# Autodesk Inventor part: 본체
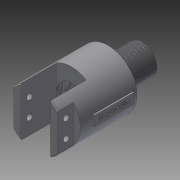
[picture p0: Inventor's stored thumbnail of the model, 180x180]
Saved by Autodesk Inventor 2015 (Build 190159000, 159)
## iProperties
Created: 2019-02
Part Number: 본체
Material: 일반
Document SubType Name: Modeling
Designer: now
Density: 1 g/cm^3
Appearance: 기본값
Author: now
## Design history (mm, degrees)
sketch "스케치1"
  geometry: C1 r 29 at (0, 0); 1 further point
  constraints: 1 centre point, 1 coincident
  dimensions: "d0" = 58 diameter of C1
extrude "돌출1" new body sketch "스케치1" distance "d1" = 74; taper "d2" = 0 deg
sketch "스케치2"
  geometry: C1 r 29 at (0, 0) reference; C2 r 13 at (0, 0)
  constraints: 1 centre point, 1 coincident
  dimensions: "d3" = 26 diameter of C2
extrude "돌출2" join sketch "스케치2" distance "d4" = 5; taper "d5" = 0 deg
sketch "스케치3"
  geometry: C1 r 13 at (0, 0) reference; C2 r 15 at (0, 0)
  constraints: 1 centre point, 1 coincident
  dimensions: "d6" = 30 diameter of C2
extrude "돌출3" join sketch "스케치3" distance "d7" = 29; taper "d8" = 0 deg
sketch "스케치4"
  geometry: L1 (-29, 0)-(-29, 74) reference; L2 (-29, 74)-(-13, 74) reference; L3 (-13, 74)-(-13, 79) reference; L4 (-13, 79)-(-15, 79) reference; L5 (-15, 79)-(-15, 108) reference; L6 (-15, 108)-(15, 108) reference; L7 (15, 108)-(15, 79) reference; L8 (15, 79)-(13, 79) reference; L9 (13, 79)-(13, 74) reference; L10 (13, 74)-(29, 74) reference; L11 (29, 74)-(29, 0) reference; L12 (29, 0)-(-29, 0) reference; L13 (15, 36)-(-15, 36); L14 (-15, 36)-(-15, 0); L15 (-15, 0)-(15, 0); L16 (15, 0)-(15, 36); L17 (15, 36)-(-15, 0); L18 (-15, 36)-(15, 0); 4 further points
  constraints: 12 end point, 4 midpoint, 2 parallel, 1 horizontal, 1 perpendicular, 1 point on line, 1 vertical alignment
  dimensions: "d9" = 36 distance of L15.end L13.start; "d10" = 30 distance of L13.start L13.end
extrude "돌출4" cut sketch "스케치4" stored distance "d11" = 29; taper "d12" = 0 deg
sketch "스케치5"
  geometry: L1 (-13, 79)-(-15, 79) reference; L2 (-15, 79)-(-15, 108) reference; L3 (-15, 108)-(15, 108) reference; L4 (15, 108)-(15, 79) reference; L5 (15, 79)-(13, 79) reference; L6 (13, 79)-(13, 74) reference; L7 (13, 74)-(29, 74) reference; L8 (29, 74)-(29, 0) reference; L9 (29, 0)-(15, 0) reference; L10 (15, 0)-(15, 36) reference; L11 (15, 36)-(-15, 36) reference; L12 (-15, 36)-(-15, 0) reference; L13 (-15, 0)-(-29, 0) reference; L14 (-29, 0)-(-29, 74) reference; L15 (-29, 74)-(-13, 74) reference; L16 (-13, 74)-(-13, 79) reference; L17 (-29, 16)-(-22, 16); L18 (-22, 16)-(-22, 0); L19 (-22, 0)-(-29, 0); L20 (-29, 0)-(-29, 16); 1 further point
  constraints: 8 end point, 2 parallel, 1 horizontal, 1 perpendicular
  dimensions: "d14" = 22 distance from line of point (0, 0) L18; "d15" = 16 distance of L17.end L18.end
extrude "돌출5" cut sketch "스케치5" stored distance "d16" = 29; taper "d17" = 0 deg
sketch "스케치6"
  geometry: L1 (0, 0)-(-37.789, 0) reference; 2 further points
  dimensions: "d18" = 9 distance from line of L1 point (-27.894, 9); "d19" = 9 horizontal distance of point (-18.894, 0) point (-27.894, 9)
hole "구멍1" sketch "스케치6" at (-27.894, 9) diameter "d20" = 6; stored, may be unused: countersink angle "d24" = 90 deg, drill point angle "d26" = 118 deg; dims "d21" = 6, "d22" = 4, "d23" = 2, "d25" = 8
sketch "스케치8"
  geometry: L1 (79, 13)-(79, 15) reference; L2 (79, 15)-(108, 15) reference; L3 (108, 15)-(108, -15) reference; L4 (108, -15)-(79, -15) reference; L5 (79, -15)-(79, -13) reference; L6 (79, -13)-(74, -13) reference; L7 (74, -13)-(74, -29) reference; L8 (74, -29)-(36, -29) reference; L9 (36, -29)-(36, 29) reference; L10 (36, 29)-(74, 29) reference; L11 (74, 29)-(74, 13) reference; L12 (74, 13)-(79, 13) reference; L13 (36, 0)-(63, 0); L14 (63, 0)-(63, 16); L15 (63, 16)-(56, 16); L16 (56, 16)-(56, 14); L17 (56, 14)-(52.35, 14); L18 (47.65, 14)-(47.65, 17); L19 (47.65, 17)-(52.35, 17); L20 (52.35, 17)-(52.35, 14); L21 (38.65, 14)-(38.65, 17); L22 (38.65, 17)-(43.35, 17); L23 (43.35, 17)-(43.35, 14); L24 (36, 14)-(36, 0); L25 (36, -24.819)-(36, 24.819) reference; L26 (41, 21)-(41, -0.922); L27 (50, 20.712)-(50, -2.282); L28 (38.65, 14)-(36, 14); L29 (47.65, 14)-(43.35, 14); 3 further points
  constraints: 32 end point, 9 perpendicular, 6 point on line, 3 midpoint, 3 vertical, 1 collinear
  dimensions: "d36" = 5 distance between parallel lines of L9 L26; "d37" = 9 distance between parallel lines of L27 L26; "d38" = 4.7 distance between parallel lines of L23 L21; "d39" = 4.7 distance between parallel lines of L20 L18; "d40" = 17 distance between parallel lines of L13 L22; "d42" = 7 distance of L14.end L15.end; "d43" = 27 distance between parallel lines of L24 L14; "d44" = 16 distance of L13.end L14.end; "d45" = 14 distance between parallel lines of L13 L28; "d46" = 14 distance between parallel lines of L13 L29
revolve "회전1" sketch "스케치8" stored, may be unused: angle "d47" = 90 deg
feature "스레드1" dims "d48" = 10, "d49" = 0
sketch "스케치9"
  geometry: C1 r 15 at (0, 0) reference
hole "구멍2" sketch "스케치9" at (0, 0) diameter "d50" = 12.376; stored, may be unused: countersink angle "d54" = 90 deg, drill point angle "d56" = 0 deg; dims "d51" = 18, "d52" = 28, "d53" = 2, "d55" = 22
sketch "스케치10"
  geometry: C1 r 6.188 at (0, 0) reference
hole "구멍3" sketch "스케치10" at (0, 0) diameter "d57" = 8; stored, may be unused: countersink angle "d61" = 90 deg, drill point angle "d63" = 0 deg; dims "d58" = 18, "d59" = 28, "d60" = 2, "d62" = 22
node "작업 평면1"
sketch "스케치11"
  geometry: L1 (29, 5)-(69, 5); L2 (69, 5)-(69, -5); L3 (69, -5)-(29, -5); L4 (29, -5)-(29, 5); L5 (74, -29)-(74, 29) reference; 2 further points
  constraints: 8 end point, 2 parallel, 1 horizontal, 1 horizontal alignment, 1 midpoint, 1 perpendicular
  dimensions: "d65" = 10 distance of L3.end L1.start; "d66" = 40 distance of L1.start L1.end; "d67" = 5 distance between parallel lines of L5 L2
extrude "돌출6" join sketch "스케치11" stored distance "d68" = 29; taper "d69" = 0 deg
sketch "스케치12"
  geometry: L1 (-5, 29)-(-5, 69) reference; L2 (5, 29)-(-5, 29) reference; 4 further points
  constraints: 2 midpoint, 1 horizontal alignment, 1 vertical alignment, 1 other
feature "엠보싱1" sketch "스케치12" dims "d70" = 0.5, "d71" = 0
fillet "모깎기1" dims "d72" = 0.8
chamfer "모따기1" distance "d73" = 1; stored, may be unused: second distance "d74" = 2, angle "d75" = 45 deg
chamfer "모따기2" distance "d76" = 1; stored, may be unused: second distance "d77" = 2, angle "d78" = 45 deg
chamfer "모따기3" distance "d79" = 1; stored, may be unused: second distance "d80" = 2, angle "d81" = 45 deg
node "솔리드1"
mirror "대칭1"
mirror "대칭2"
node "절단 모서리 투영1"
node "절단 모서리 투영2"
node "절단 모서리 투영4"
other parameters: "d41" = 14
